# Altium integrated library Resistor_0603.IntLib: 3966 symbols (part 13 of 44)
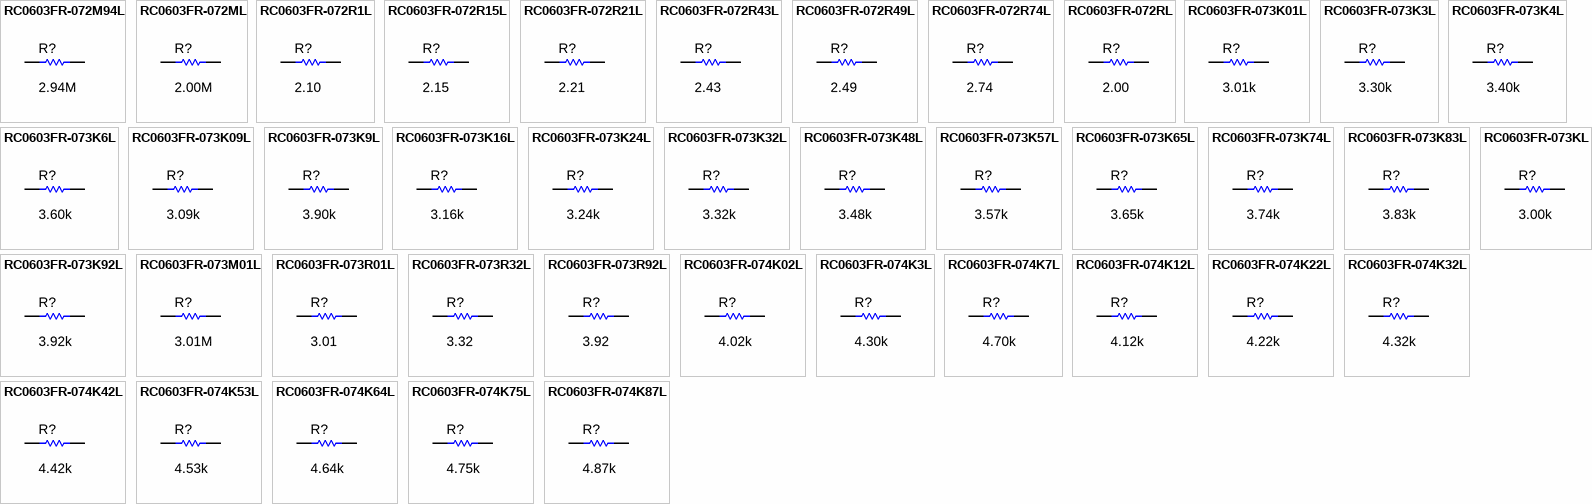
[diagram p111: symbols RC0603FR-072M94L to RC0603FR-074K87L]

## RC0603FR-074K53L
designator R?  ValueDisplayed: 4.53k  (hidden comment: RC0603FR-074K53L)
RES, 4.53 k, 1%, 0.1 W, 0603; Manufacturer: Yageo America; CompType: Resistor; Value: 4.53k; Res_ohm: 4530; Value_Code: 4k53; Tolerance_%: 1; Power_W: 0.1; Value2: 0.1W; VDC_V: 150; TempCo: 200 ppm/C; SizeArea_mm2: 1.28; SizeX_mm: 1.6; SizeY_mm: 0.8; EIA_Code: E96; U/M: EA; AEC Category: Q200
signal-integrity model Resistor
simulation model Resistor
footprint 0603
footprint 0603M
footprint 0603L
footprint 0603_HV
footprint 0603S
pins: 1, 2

## RC0603FR-074K64L
designator R?  ValueDisplayed: 4.64k  (hidden comment: RC0603FR-074K64L)
RES, 4.64 k, 1%, 0.1 W, 0603; Manufacturer: Yageo America; CompType: Resistor; Value: 4.64k; Res_ohm: 4640; Value_Code: 4k64; Tolerance_%: 1; Power_W: 0.1; Value2: 0.1W; VDC_V: 150; TempCo: 200 ppm/C; SizeArea_mm2: 1.28; SizeX_mm: 1.6; SizeY_mm: 0.8; EIA_Code: E96; U/M: EA; AEC Category: Q200; Green_Lifecycle: Active; Green_REACh: Passed
signal-integrity model Resistor
simulation model Resistor
footprint 0603
footprint 0603M
footprint 0603L
footprint 0603_HV
footprint 0603S
pins: 1, 2

## RC0603FR-074K75L
designator R?  ValueDisplayed: 4.75k  (hidden comment: RC0603FR-074K75L)
RES, 4.75 k, 1%, 0.1 W, 0603; Manufacturer: Yageo America; CompType: Resistor; Value: 4.75k; Res_ohm: 4750; Value_Code: 4k75; Tolerance_%: 1; Power_W: 0.1; Value2: 0.1W; VDC_V: 150; TempCo: 200 ppm/C; SizeArea_mm2: 1.28; SizeX_mm: 1.6; SizeY_mm: 0.8; EIA_Code: E96; U/M: EA; AEC Category: Q200
signal-integrity model Resistor
simulation model Resistor
footprint 0603
footprint 0603M
footprint 0603L
footprint 0603_HV
footprint 0603S
pins: 1, 2

## RC0603FR-074K87L
designator R?  ValueDisplayed: 4.87k  (hidden comment: RC0603FR-074K87L)
RES, 4.87 k, 1%, 0.1 W, 0603; Manufacturer: Yageo America; CompType: Resistor; Value: 4.87k; Res_ohm: 4870; Value_Code: 4k87; Tolerance_%: 1; Power_W: 0.1; Value2: 0.1W; VDC_V: 150; TempCo: 200 ppm/C; SizeArea_mm2: 1.28; SizeX_mm: 1.6; SizeY_mm: 0.8; EIA_Code: E96; U/M: EA; AEC Category: Q200; Green_Lifecycle: Active; Green_REACh: Passed
signal-integrity model Resistor
simulation model Resistor
footprint 0603
footprint 0603M
footprint 0603L
footprint 0603_HV
footprint 0603S
pins: 1, 2

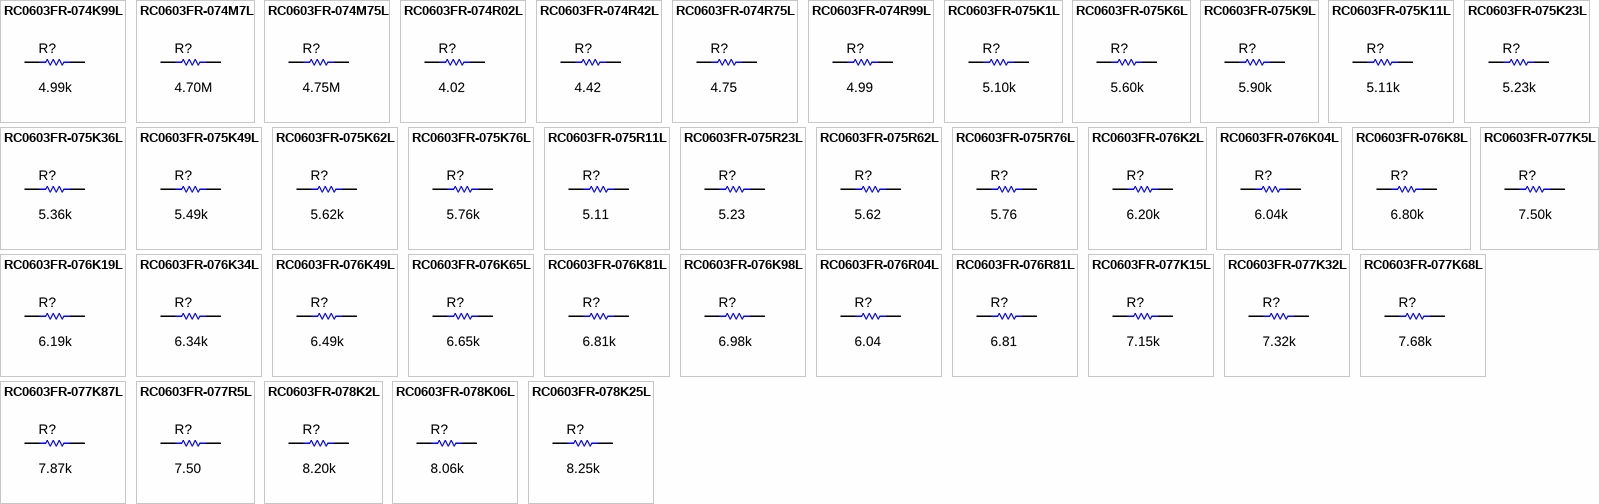
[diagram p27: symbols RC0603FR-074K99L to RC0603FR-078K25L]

## RC0603FR-074K99L
designator R?  ValueDisplayed: 4.99k  (hidden comment: RC0603FR-074K99L)
RES, 4.99 k, 1%, 0.1 W, 0603; Manufacturer: Yageo America; CompType: Resistor; Value: 4.99k; Res_ohm: 4990; Value_Code: 4k99; Tolerance_%: 1; Power_W: 0.1; Value2: 0.1W; VDC_V: 150; TempCo: 200 ppm/C; SizeArea_mm2: 1.28; SizeX_mm: 1.6; SizeY_mm: 0.8; EIA_Code: E96; U/M: EA; AEC Category: Q200; Green_Lifecycle: Active; Green_REACh: Passed
signal-integrity model Resistor
simulation model Resistor
footprint 0603
footprint 0603M
footprint 0603L
footprint 0603_HV
footprint 0603S
pins: 1, 2

## RC0603FR-074M7L
designator R?  ValueDisplayed: 4.70M  (hidden comment: RC0603FR-074M7L)
RES, 4.70 M, 1%, 0.1 W, 0603; Manufacturer: Yageo America; CompType: Resistor; Value: 4.70Meg; Res_ohm: 4700000; Value_Code: 4M70; Tolerance_%: 1; Power_W: 0.1; Value2: 0.1W; VDC_V: 150; TempCo: 200 ppm/C; SizeArea_mm2: 1.28; SizeX_mm: 1.6; SizeY_mm: 0.8; U/M: EA; AEC Category: Q200
signal-integrity model Resistor
simulation model Resistor
footprint 0603
footprint 0603M
footprint 0603L
footprint 0603_HV
footprint 0603S
pins: 1, 2

## RC0603FR-074M75L
designator R?  ValueDisplayed: 4.75M  (hidden comment: RC0603FR-074M75L)
RES, 4.75 M, 1%, 0.1 W, 0603; Manufacturer: Yageo America; CompType: Resistor; Value: 4.75Meg; Res_ohm: 4750000; Value_Code: 4M75; Tolerance_%: 1; Power_W: 0.1; Value2: 0.1W; VDC_V: 150; TempCo: 200 ppm/C; SizeArea_mm2: 1.28; SizeX_mm: 1.6; SizeY_mm: 0.8; EIA_Code: E96; U/M: EA; AEC Category: Q200
signal-integrity model Resistor
simulation model Resistor
footprint 0603
footprint 0603M
footprint 0603L
footprint 0603_HV
footprint 0603S
pins: 1, 2

## RC0603FR-074R02L
designator R?  ValueDisplayed: 4.02  (hidden comment: RC0603FR-074R02L)
RES, 4.02, 1%, 0.1 W, 0603; Manufacturer: Yageo America; CompType: Resistor; Value: 4.02; Value_Code: 4R02; Tolerance_%: 1; Power_W: 0.1; Value2: 0.1W; VDC_V: 150; TempCo: 200 ppm/C; SizeArea_mm2: 1.28; SizeX_mm: 1.6; SizeY_mm: 0.8; EIA_Code: E96; U/M: EA; AEC Category: Q200
signal-integrity model Resistor
simulation model Resistor
footprint 0603
footprint 0603M
footprint 0603L
footprint 0603_HV
footprint 0603S
pins: 1, 2

## RC0603FR-074R42L
designator R?  ValueDisplayed: 4.42  (hidden comment: RC0603FR-074R42L)
RES, 4.42, 1%, 0.1 W, 0603; Manufacturer: Yageo America; CompType: Resistor; Value: 4.42; Value_Code: 4R42; Tolerance_%: 1; Power_W: 0.1; Value2: 0.1W; VDC_V: 150; TempCo: 200 ppm/C; SizeArea_mm2: 1.28; SizeX_mm: 1.6; SizeY_mm: 0.8; EIA_Code: E96; U/M: EA; AEC Category: Q200
signal-integrity model Resistor
simulation model Resistor
footprint 0603
footprint 0603M
footprint 0603L
footprint 0603_HV
footprint 0603S
pins: 1, 2

## RC0603FR-074R75L
designator R?  ValueDisplayed: 4.75  (hidden comment: RC0603FR-074R75L)
RES, 4.75, 1%, 0.1 W, 0603; Manufacturer: Yageo America; CompType: Resistor; Value: 4.75; Value_Code: 4R75; Tolerance_%: 1; Power_W: 0.1; Value2: 0.1W; VDC_V: 150; TempCo: 200 ppm/C; SizeArea_mm2: 1.28; SizeX_mm: 1.6; SizeY_mm: 0.8; EIA_Code: E96; U/M: EA; AEC Category: Q200
signal-integrity model Resistor
simulation model Resistor
footprint 0603
footprint 0603M
footprint 0603L
footprint 0603_HV
footprint 0603S
pins: 1, 2

## RC0603FR-074R99L
designator R?  ValueDisplayed: 4.99  (hidden comment: RC0603FR-074R99L)
RES, 4.99, 1%, 0.1 W, 0603; Manufacturer: Yageo America; CompType: Resistor; Value: 4.99; Value_Code: 4R99; Tolerance_%: 1; Power_W: 0.1; Value2: 0.1W; VDC_V: 150; TempCo: 200 ppm/C; SizeArea_mm2: 1.28; SizeX_mm: 1.6; SizeY_mm: 0.8; EIA_Code: E96; U/M: EA; AEC Category: Q200; Green_Lifecycle: Active; Green_REACh: Passed
signal-integrity model Resistor
simulation model Resistor
footprint 0603
footprint 0603M
footprint 0603L
footprint 0603_HV
footprint 0603S
pins: 1, 2

## RC0603FR-075K1L
designator R?  ValueDisplayed: 5.10k  (hidden comment: RC0603FR-075K1L)
RES, 5.10 k, 1%, 0.1 W, 0603; Manufacturer: Yageo America; CompType: Resistor; Value: 5.10k; Res_ohm: 5100; Value_Code: 5k10; Tolerance_%: 1; Power_W: 0.1; Value2: 0.1W; VDC_V: 150; TempCo: 200 ppm/C; SizeArea_mm2: 1.28; SizeX_mm: 1.6; SizeY_mm: 0.8; U/M: EA; AEC Category: Q200; Green_Lifecycle: Active; Green_REACh: Passed
signal-integrity model Resistor
simulation model Resistor
footprint 0603
footprint 0603M
footprint 0603L
footprint 0603_HV
footprint 0603S
pins: 1, 2

## RC0603FR-075K6L
designator R?  ValueDisplayed: 5.60k  (hidden comment: RC0603FR-075K6L)
RES, 5.60 k, 1%, 0.1 W, 0603; Manufacturer: Yageo America; CompType: Resistor; Value: 5.60k; Res_ohm: 5600; Value_Code: 5k60; Tolerance_%: 1; Power_W: 0.1; Value2: 0.1W; VDC_V: 150; TempCo: 200 ppm/C; SizeArea_mm2: 1.28; SizeX_mm: 1.6; SizeY_mm: 0.8; U/M: EA; AEC Category: Q200; Green_Lifecycle: Active; Green_REACh: Passed
signal-integrity model Resistor
simulation model Resistor
footprint 0603
footprint 0603M
footprint 0603L
footprint 0603_HV
footprint 0603S
pins: 1, 2

## RC0603FR-075K9L
designator R?  ValueDisplayed: 5.90k  (hidden comment: RC0603FR-075K9L)
RES, 5.90 k, 1%, 0.1 W, 0603; Manufacturer: Yageo America; CompType: Resistor; Value: 5.90k; Res_ohm: 5900; Value_Code: 5k90; Tolerance_%: 1; Power_W: 0.1; Value2: 0.1W; VDC_V: 150; TempCo: 200 ppm/C; SizeArea_mm2: 1.28; SizeX_mm: 1.6; SizeY_mm: 0.8; EIA_Code: E96; U/M: EA; AEC Category: Q200; Green_Lifecycle: Active; Green_REACh: Passed
signal-integrity model Resistor
simulation model Resistor
footprint 0603
footprint 0603M
footprint 0603L
footprint 0603_HV
footprint 0603S
pins: 1, 2

## RC0603FR-075K11L
designator R?  ValueDisplayed: 5.11k  (hidden comment: RC0603FR-075K11L)
RES, 5.11 k, 1%, 0.1 W, 0603; Manufacturer: Yageo America; CompType: Resistor; Value: 5.11k; Res_ohm: 5110; Value_Code: 5k11; Tolerance_%: 1; Power_W: 0.1; Value2: 0.1W; VDC_V: 150; TempCo: 200 ppm/C; SizeArea_mm2: 1.28; SizeX_mm: 1.6; SizeY_mm: 0.8; EIA_Code: E96; U/M: EA; AEC Category: Q200; Green_Lifecycle: Active; Green_REACh: Passed
signal-integrity model Resistor
simulation model Resistor
footprint 0603
footprint 0603M
footprint 0603L
footprint 0603_HV
footprint 0603S
pins: 1, 2

## RC0603FR-075K23L
designator R?  ValueDisplayed: 5.23k  (hidden comment: RC0603FR-075K23L)
RES, 5.23 k, 1%, 0.1 W, 0603; Manufacturer: Yageo America; CompType: Resistor; Value: 5.23k; Res_ohm: 5230; Value_Code: 5k23; Tolerance_%: 1; Power_W: 0.1; Value2: 0.1W; VDC_V: 150; TempCo: 200 ppm/C; SizeArea_mm2: 1.28; SizeX_mm: 1.6; SizeY_mm: 0.8; EIA_Code: E96; U/M: EA; AEC Category: Q200; Green_Lifecycle: Active; Green_REACh: Passed
signal-integrity model Resistor
simulation model Resistor
footprint 0603
footprint 0603M
footprint 0603L
footprint 0603_HV
footprint 0603S
pins: 1, 2

## RC0603FR-075K36L
designator R?  ValueDisplayed: 5.36k  (hidden comment: RC0603FR-075K36L)
RES, 5.36 k, 1%, 0.1 W, 0603; Manufacturer: Yageo America; CompType: Resistor; Value: 5.36k; Res_ohm: 5360; Value_Code: 5k36; Tolerance_%: 1; Power_W: 0.1; Value2: 0.1W; VDC_V: 150; TempCo: 200 ppm/C; SizeArea_mm2: 1.28; SizeX_mm: 1.6; SizeY_mm: 0.8; EIA_Code: E96; U/M: EA; AEC Category: Q200; Green_Lifecycle: Active; Green_REACh: Passed
signal-integrity model Resistor
simulation model Resistor
footprint 0603
footprint 0603M
footprint 0603L
footprint 0603_HV
footprint 0603S
pins: 1, 2

## RC0603FR-075K49L
designator R?  ValueDisplayed: 5.49k  (hidden comment: RC0603FR-075K49L)
RES, 5.49 k, 1%, 0.1 W, 0603; Manufacturer: Yageo America; CompType: Resistor; Value: 5.49k; Res_ohm: 5490; Value_Code: 5k49; Tolerance_%: 1; Power_W: 0.1; Value2: 0.1W; VDC_V: 150; TempCo: 200 ppm/C; SizeArea_mm2: 1.28; SizeX_mm: 1.6; SizeY_mm: 0.8; EIA_Code: E96; U/M: EA; AEC Category: Q200
signal-integrity model Resistor
simulation model Resistor
footprint 0603
footprint 0603M
footprint 0603L
footprint 0603_HV
footprint 0603S
pins: 1, 2

## RC0603FR-075K62L
designator R?  ValueDisplayed: 5.62k  (hidden comment: RC0603FR-075K62L)
RES, 5.62 k, 1%, 0.1 W, 0603; Manufacturer: Yageo America; CompType: Resistor; Value: 5.62k; Res_ohm: 5620; Value_Code: 5k62; Tolerance_%: 1; Power_W: 0.1; Value2: 0.1W; VDC_V: 150; TempCo: 200 ppm/C; SizeArea_mm2: 1.28; SizeX_mm: 1.6; SizeY_mm: 0.8; EIA_Code: E96; U/M: EA; AEC Category: Q200; Green_Lifecycle: Active; Green_REACh: Passed
signal-integrity model Resistor
simulation model Resistor
footprint 0603
footprint 0603M
footprint 0603L
footprint 0603_HV
footprint 0603S
pins: 1, 2

## RC0603FR-075K76L
designator R?  ValueDisplayed: 5.76k  (hidden comment: RC0603FR-075K76L)
RES, 5.76 k, 1%, 0.1 W, 0603; Manufacturer: Yageo America; CompType: Resistor; Value: 5.76k; Res_ohm: 5760; Value_Code: 5k76; Tolerance_%: 1; Power_W: 0.1; Value2: 0.1W; VDC_V: 150; TempCo: 200 ppm/C; SizeArea_mm2: 1.28; SizeX_mm: 1.6; SizeY_mm: 0.8; EIA_Code: E96; U/M: EA; AEC Category: Q200
signal-integrity model Resistor
simulation model Resistor
footprint 0603
footprint 0603M
footprint 0603L
footprint 0603_HV
footprint 0603S
pins: 1, 2

## RC0603FR-075R11L
designator R?  ValueDisplayed: 5.11  (hidden comment: RC0603FR-075R11L)
RES, 5.11, 1%, 0.1 W, 0603; Manufacturer: Yageo America; CompType: Resistor; Value: 5.11; Value_Code: 5R11; Tolerance_%: 1; Power_W: 0.1; Value2: 0.1W; VDC_V: 150; TempCo: 200 ppm/C; SizeArea_mm2: 1.28; SizeX_mm: 1.6; SizeY_mm: 0.8; EIA_Code: E96; U/M: EA; AEC Category: Q200
signal-integrity model Resistor
simulation model Resistor
footprint 0603
footprint 0603M
footprint 0603L
footprint 0603_HV
footprint 0603S
pins: 1, 2

## RC0603FR-075R23L
designator R?  ValueDisplayed: 5.23  (hidden comment: RC0603FR-075R23L)
RES, 5.23, 1%, 0.1 W, 0603; Manufacturer: Yageo America; CompType: Resistor; Value: 5.23; Value_Code: 5R23; Tolerance_%: 1; Power_W: 0.1; Value2: 0.1W; VDC_V: 150; TempCo: 200 ppm/C; SizeArea_mm2: 1.28; SizeX_mm: 1.6; SizeY_mm: 0.8; EIA_Code: E96; U/M: EA; AEC Category: Q200
signal-integrity model Resistor
simulation model Resistor
footprint 0603
footprint 0603M
footprint 0603L
footprint 0603_HV
footprint 0603S
pins: 1, 2

## RC0603FR-075R62L
designator R?  ValueDisplayed: 5.62  (hidden comment: RC0603FR-075R62L)
RES, 5.62, 1%, 0.1 W, 0603; Manufacturer: Yageo America; CompType: Resistor; Value: 5.62; Value_Code: 5R62; Tolerance_%: 1; Power_W: 0.1; Value2: 0.1W; VDC_V: 150; TempCo: 200 ppm/C; SizeArea_mm2: 1.28; SizeX_mm: 1.6; SizeY_mm: 0.8; EIA_Code: E96; U/M: EA; AEC Category: Q200
signal-integrity model Resistor
simulation model Resistor
footprint 0603
footprint 0603M
footprint 0603L
footprint 0603_HV
footprint 0603S
pins: 1, 2

## RC0603FR-075R76L
designator R?  ValueDisplayed: 5.76  (hidden comment: RC0603FR-075R76L)
RES, 5.76, 1%, 0.1 W, 0603; Manufacturer: Yageo America; CompType: Resistor; Value: 5.76; Value_Code: 5R76; Tolerance_%: 1; Power_W: 0.1; Value2: 0.1W; VDC_V: 150; TempCo: 200 ppm/C; SizeArea_mm2: 1.28; SizeX_mm: 1.6; SizeY_mm: 0.8; EIA_Code: E96; U/M: EA; AEC Category: Q200
signal-integrity model Resistor
simulation model Resistor
footprint 0603
footprint 0603M
footprint 0603L
footprint 0603_HV
footprint 0603S
pins: 1, 2

## RC0603FR-076K2L
designator R?  ValueDisplayed: 6.20k  (hidden comment: RC0603FR-076K2L)
RES, 6.20 k, 1%, 0.1 W, 0603; Manufacturer: Yageo America; CompType: Resistor; Value: 6.20k; Res_ohm: 6200; Value_Code: 6k20; Tolerance_%: 1; Power_W: 0.1; Value2: 0.1W; VDC_V: 150; TempCo: 200 ppm/C; SizeArea_mm2: 1.28; SizeX_mm: 1.6; SizeY_mm: 0.8; U/M: EA; AEC Category: Q200
signal-integrity model Resistor
simulation model Resistor
footprint 0603
footprint 0603M
footprint 0603L
footprint 0603_HV
footprint 0603S
pins: 1, 2

## RC0603FR-076K04L
designator R?  ValueDisplayed: 6.04k  (hidden comment: RC0603FR-076K04L)
RES, 6.04 k, 1%, 0.1 W, 0603; Manufacturer: Yageo America; CompType: Resistor; Value: 6.04k; Res_ohm: 6040; Value_Code: 6k04; Tolerance_%: 1; Power_W: 0.1; Value2: 0.1W; VDC_V: 150; TempCo: 200 ppm/C; SizeArea_mm2: 1.28; SizeX_mm: 1.6; SizeY_mm: 0.8; EIA_Code: E96; U/M: EA; AEC Category: Q200; Green_Lifecycle: Active; Green_REACh: Passed
signal-integrity model Resistor
simulation model Resistor
footprint 0603
footprint 0603M
footprint 0603L
footprint 0603_HV
footprint 0603S
pins: 1, 2

## RC0603FR-076K8L
designator R?  ValueDisplayed: 6.80k  (hidden comment: RC0603FR-076K8L)
RES, 6.80 k, 1%, 0.1 W, 0603; Manufacturer: Yageo America; CompType: Resistor; Value: 6.80k; Res_ohm: 6800; Value_Code: 6k80; Tolerance_%: 1; Power_W: 0.1; Value2: 0.1W; VDC_V: 150; TempCo: 200 ppm/C; SizeArea_mm2: 1.28; SizeX_mm: 1.6; SizeY_mm: 0.8; U/M: EA; AEC Category: Q200; Green_Lifecycle: Active; Green_REACh: Passed
signal-integrity model Resistor
simulation model Resistor
footprint 0603
footprint 0603M
footprint 0603L
footprint 0603_HV
footprint 0603S
pins: 1, 2

## RC0603FR-076K19L
designator R?  ValueDisplayed: 6.19k  (hidden comment: RC0603FR-076K19L)
RES, 6.19 k, 1%, 0.1 W, 0603; Manufacturer: Yageo America; CompType: Resistor; Value: 6.19k; Res_ohm: 6190; Value_Code: 6k19; Tolerance_%: 1; Power_W: 0.1; Value2: 0.1W; VDC_V: 150; TempCo: 200 ppm/C; SizeArea_mm2: 1.28; SizeX_mm: 1.6; SizeY_mm: 0.8; EIA_Code: E96; U/M: EA; AEC Category: Q200
signal-integrity model Resistor
simulation model Resistor
footprint 0603
footprint 0603M
footprint 0603L
footprint 0603_HV
footprint 0603S
pins: 1, 2

## RC0603FR-076K34L
designator R?  ValueDisplayed: 6.34k  (hidden comment: RC0603FR-076K34L)
RES, 6.34 k, 1%, 0.1 W, 0603; Manufacturer: Yageo America; CompType: Resistor; Value: 6.34k; Res_ohm: 6340; Value_Code: 6k34; Tolerance_%: 1; Power_W: 0.1; Value2: 0.1W; VDC_V: 150; TempCo: 200 ppm/C; SizeArea_mm2: 1.28; SizeX_mm: 1.6; SizeY_mm: 0.8; EIA_Code: E96; U/M: EA; AEC Category: Q200
signal-integrity model Resistor
simulation model Resistor
footprint 0603
footprint 0603M
footprint 0603L
footprint 0603_HV
footprint 0603S
pins: 1, 2

## RC0603FR-076K49L
designator R?  ValueDisplayed: 6.49k  (hidden comment: RC0603FR-076K49L)
RES, 6.49 k, 1%, 0.1 W, 0603; Manufacturer: Yageo America; CompType: Resistor; Value: 6.49k; Res_ohm: 6490; Value_Code: 6k49; Tolerance_%: 1; Power_W: 0.1; Value2: 0.1W; VDC_V: 150; TempCo: 200 ppm/C; SizeArea_mm2: 1.28; SizeX_mm: 1.6; SizeY_mm: 0.8; EIA_Code: E96; U/M: EA; AEC Category: Q200; Green_Lifecycle: Not Set; Green_REACh: Incomplete
signal-integrity model Resistor
simulation model Resistor
footprint 0603
footprint 0603M
footprint 0603L
footprint 0603_HV
footprint 0603S
pins: 1, 2

## RC0603FR-076K65L
designator R?  ValueDisplayed: 6.65k  (hidden comment: RC0603FR-076K65L)
RES, 6.65 k, 1%, 0.1 W, 0603; Manufacturer: Yageo America; CompType: Resistor; Value: 6.65k; Res_ohm: 6650; Value_Code: 6k65; Tolerance_%: 1; Power_W: 0.1; Value2: 0.1W; VDC_V: 150; TempCo: 200 ppm/C; SizeArea_mm2: 1.28; SizeX_mm: 1.6; SizeY_mm: 0.8; EIA_Code: E96; U/M: EA; AEC Category: Q200; Green_Lifecycle: Active; Green_REACh: Passed
signal-integrity model Resistor
simulation model Resistor
footprint 0603
footprint 0603M
footprint 0603L
footprint 0603_HV
footprint 0603S
pins: 1, 2

## RC0603FR-076K81L
designator R?  ValueDisplayed: 6.81k  (hidden comment: RC0603FR-076K81L)
RES, 6.81 k, 1%, 0.1 W, 0603; Manufacturer: Yageo America; CompType: Resistor; Value: 6.81k; Res_ohm: 6810; Value_Code: 6k81; Tolerance_%: 1; Power_W: 0.1; Value2: 0.1W; VDC_V: 150; TempCo: 200 ppm/C; SizeArea_mm2: 1.28; SizeX_mm: 1.6; SizeY_mm: 0.8; EIA_Code: E96; U/M: EA; AEC Category: Q200
signal-integrity model Resistor
simulation model Resistor
footprint 0603
footprint 0603M
footprint 0603L
footprint 0603_HV
footprint 0603S
pins: 1, 2

## RC0603FR-076K98L
designator R?  ValueDisplayed: 6.98k  (hidden comment: RC0603FR-076K98L)
RES, 6.98 k, 1%, 0.1 W, 0603; Manufacturer: Yageo America; CompType: Resistor; Value: 6.98k; Res_ohm: 6980; Value_Code: 6k98; Tolerance_%: 1; Power_W: 0.1; Value2: 0.1W; VDC_V: 150; TempCo: 200 ppm/C; SizeArea_mm2: 1.28; SizeX_mm: 1.6; SizeY_mm: 0.8; EIA_Code: E96; U/M: EA; AEC Category: Q200; Green_Lifecycle: Active; Green_REACh: Passed
signal-integrity model Resistor
simulation model Resistor
footprint 0603
footprint 0603M
footprint 0603L
footprint 0603_HV
footprint 0603S
pins: 1, 2

## RC0603FR-076R04L
designator R?  ValueDisplayed: 6.04  (hidden comment: RC0603FR-076R04L)
RES, 6.04, 1%, 0.1 W, 0603; Manufacturer: Yageo America; CompType: Resistor; Value: 6.04; Value_Code: 6R04; Tolerance_%: 1; Power_W: 0.1; Value2: 0.1W; VDC_V: 150; TempCo: 200 ppm/C; SizeArea_mm2: 1.28; SizeX_mm: 1.6; SizeY_mm: 0.8; EIA_Code: E96; U/M: EA; AEC Category: Q200
signal-integrity model Resistor
simulation model Resistor
footprint 0603
footprint 0603M
footprint 0603L
footprint 0603_HV
footprint 0603S
pins: 1, 2

## RC0603FR-076R81L
designator R?  ValueDisplayed: 6.81  (hidden comment: RC0603FR-076R81L)
RES, 6.81, 1%, 0.1 W, 0603; Manufacturer: Yageo America; CompType: Resistor; Value: 6.81; Value_Code: 6R81; Tolerance_%: 1; Power_W: 0.1; Value2: 0.1W; VDC_V: 150; TempCo: 200 ppm/C; SizeArea_mm2: 1.28; SizeX_mm: 1.6; SizeY_mm: 0.8; EIA_Code: E96; U/M: EA; AEC Category: Q200
signal-integrity model Resistor
simulation model Resistor
footprint 0603
footprint 0603M
footprint 0603L
footprint 0603_HV
footprint 0603S
pins: 1, 2

## RC0603FR-077K5L
designator R?  ValueDisplayed: 7.50k  (hidden comment: RC0603FR-077K5L)
RES, 7.50 k, 1%, 0.1 W, 0603; Manufacturer: Yageo America; CompType: Resistor; Value: 7.50k; Res_ohm: 7500; Value_Code: 7k50; Tolerance_%: 1; Power_W: 0.1; Value2: 0.1W; VDC_V: 150; TempCo: 200 ppm/C; SizeArea_mm2: 1.28; SizeX_mm: 1.6; SizeY_mm: 0.8; EIA_Code: E96; U/M: EA; AEC Category: Q200; Green_Lifecycle: Active; Green_REACh: Passed
signal-integrity model Resistor
simulation model Resistor
footprint 0603
footprint 0603M
footprint 0603L
footprint 0603_HV
footprint 0603S
pins: 1, 2

## RC0603FR-077K15L
designator R?  ValueDisplayed: 7.15k  (hidden comment: RC0603FR-077K15L)
RES, 7.15 k, 1%, 0.1 W, 0603; Manufacturer: Yageo America; CompType: Resistor; Value: 7.15k; Res_ohm: 7150; Value_Code: 7k15; Tolerance_%: 1; Power_W: 0.1; Value2: 0.1W; VDC_V: 150; TempCo: 200 ppm/C; SizeArea_mm2: 1.28; SizeX_mm: 1.6; SizeY_mm: 0.8; EIA_Code: E96; U/M: EA; AEC Category: Q200; Green_Lifecycle: Active; Green_REACh: Passed
signal-integrity model Resistor
simulation model Resistor
footprint 0603
footprint 0603M
footprint 0603L
footprint 0603_HV
footprint 0603S
pins: 1, 2

## RC0603FR-077K32L
designator R?  ValueDisplayed: 7.32k  (hidden comment: RC0603FR-077K32L)
RES, 7.32 k, 1%, 0.1 W, 0603; Manufacturer: Yageo America; CompType: Resistor; Value: 7.32k; Res_ohm: 7320; Value_Code: 7k32; Tolerance_%: 1; Power_W: 0.1; Value2: 0.1W; VDC_V: 150; TempCo: 200 ppm/C; SizeArea_mm2: 1.28; SizeX_mm: 1.6; SizeY_mm: 0.8; EIA_Code: E96; U/M: EA; AEC Category: Q200
signal-integrity model Resistor
simulation model Resistor
footprint 0603
footprint 0603M
footprint 0603L
footprint 0603_HV
footprint 0603S
pins: 1, 2

## RC0603FR-077K68L
designator R?  ValueDisplayed: 7.68k  (hidden comment: RC0603FR-077K68L)
RES, 7.68 k, 1%, 0.1 W, 0603; Manufacturer: Yageo America; CompType: Resistor; Value: 7.68k; Res_ohm: 7680; Value_Code: 7k68; Tolerance_%: 1; Power_W: 0.1; Value2: 0.1W; VDC_V: 150; TempCo: 200 ppm/C; SizeArea_mm2: 1.28; SizeX_mm: 1.6; SizeY_mm: 0.8; EIA_Code: E96; U/M: EA; AEC Category: Q200; Green_Lifecycle: Active; Green_REACh: Passed
signal-integrity model Resistor
simulation model Resistor
footprint 0603
footprint 0603M
footprint 0603L
footprint 0603_HV
footprint 0603S
pins: 1, 2

## RC0603FR-077K87L
designator R?  ValueDisplayed: 7.87k  (hidden comment: RC0603FR-077K87L)
RES, 7.87 k, 1%, 0.1 W, 0603; Manufacturer: Yageo America; CompType: Resistor; Value: 7.87k; Res_ohm: 7870; Value_Code: 7k87; Tolerance_%: 1; Power_W: 0.1; Value2: 0.1W; VDC_V: 150; TempCo: 200 ppm/C; SizeArea_mm2: 1.28; SizeX_mm: 1.6; SizeY_mm: 0.8; EIA_Code: E96; U/M: EA; AEC Category: Q200
signal-integrity model Resistor
simulation model Resistor
footprint 0603
footprint 0603M
footprint 0603L
footprint 0603_HV
footprint 0603S
pins: 1, 2

## RC0603FR-077R5L
designator R?  ValueDisplayed: 7.50  (hidden comment: RC0603FR-077R5L)
RES, 7.50, 1%, 0.1 W, 0603; Manufacturer: Yageo America; CompType: Resistor; Value: 7.50; Res_ohm: 7.5; Value_Code: 7R50; Tolerance_%: 1; Power_W: 0.1; Value2: 0.1W; VDC_V: 150; TempCo: 200 ppm/C; SizeArea_mm2: 1.28; SizeX_mm: 1.6; SizeY_mm: 0.8; EIA_Code: E96; U/M: EA; AEC Category: Q200
signal-integrity model Resistor
simulation model Resistor
footprint 0603
footprint 0603M
footprint 0603L
footprint 0603_HV
footprint 0603S
pins: 1, 2

## RC0603FR-078K2L
designator R?  ValueDisplayed: 8.20k  (hidden comment: RC0603FR-078K2L)
RES, 8.20 k, 1%, 0.1 W, 0603; Manufacturer: Yageo America; CompType: Resistor; Value: 8.20k; Res_ohm: 8200; Value_Code: 8k20; Tolerance_%: 1; Power_W: 0.1; Value2: 0.1W; VDC_V: 150; TempCo: 200 ppm/C; SizeArea_mm2: 1.28; SizeX_mm: 1.6; SizeY_mm: 0.8; U/M: EA; AEC Category: Q200; Green_Lifecycle: Active; Green_REACh: Passed
signal-integrity model Resistor
simulation model Resistor
footprint 0603
footprint 0603M
footprint 0603L
footprint 0603_HV
footprint 0603S
pins: 1, 2

## RC0603FR-078K06L
designator R?  ValueDisplayed: 8.06k  (hidden comment: RC0603FR-078K06L)
RES, 8.06 k, 1%, 0.1 W, 0603; Manufacturer: Yageo America; CompType: Resistor; Value: 8.06k; Res_ohm: 8060; Value_Code: 8k06; Tolerance_%: 1; Power_W: 0.1; Value2: 0.1W; VDC_V: 150; TempCo: 200 ppm/C; SizeArea_mm2: 1.28; SizeX_mm: 1.6; SizeY_mm: 0.8; EIA_Code: E96; U/M: EA; AEC Category: Q200; Green_Lifecycle: Active; Green_REACh: Passed
signal-integrity model Resistor
simulation model Resistor
footprint 0603
footprint 0603M
footprint 0603L
footprint 0603_HV
footprint 0603S
pins: 1, 2

## RC0603FR-078K25L
designator R?  ValueDisplayed: 8.25k  (hidden comment: RC0603FR-078K25L)
RES, 8.25 k, 1%, 0.1 W, 0603; Manufacturer: Yageo America; CompType: Resistor; Value: 8.25k; Res_ohm: 8250; Value_Code: 8k25; Tolerance_%: 1; Power_W: 0.1; Value2: 0.1W; VDC_V: 150; TempCo: 200 ppm/C; SizeArea_mm2: 1.28; SizeX_mm: 1.6; SizeY_mm: 0.8; EIA_Code: E96; U/M: EA; AEC Category: Q200
signal-integrity model Resistor
simulation model Resistor
footprint 0603
footprint 0603M
footprint 0603L
footprint 0603_HV
footprint 0603S
pins: 1, 2

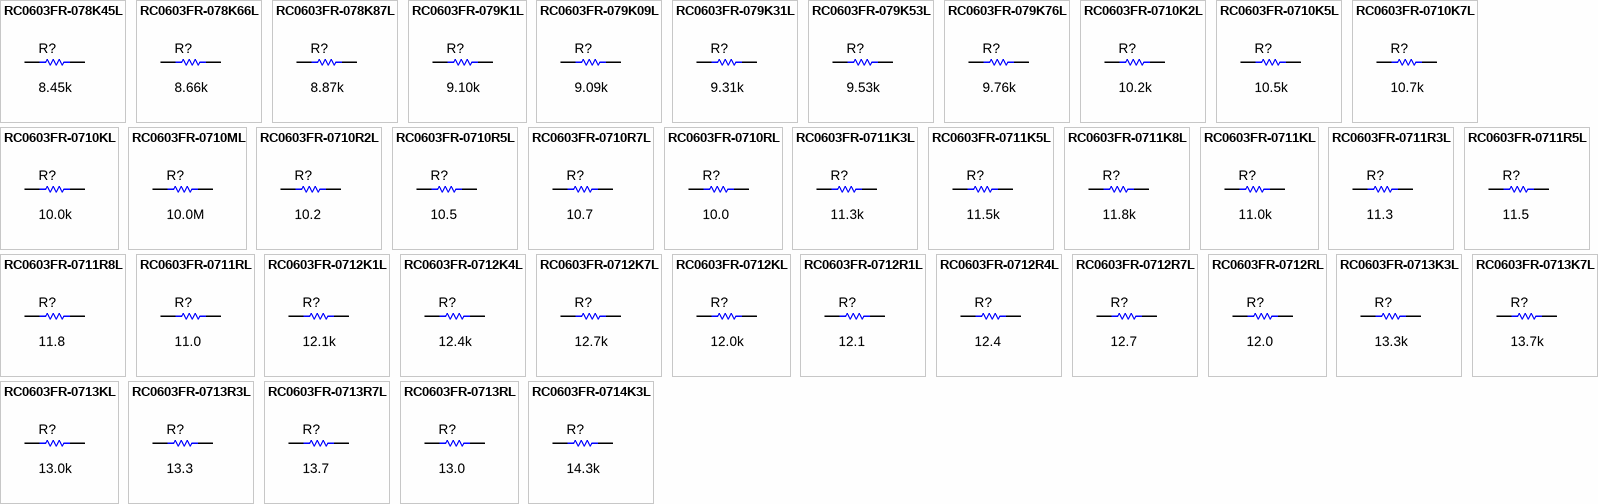
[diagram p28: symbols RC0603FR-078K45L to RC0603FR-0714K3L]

## RC0603FR-078K45L
designator R?  ValueDisplayed: 8.45k  (hidden comment: RC0603FR-078K45L)
RES, 8.45 k, 1%, 0.1 W, 0603; Manufacturer: Yageo America; CompType: Resistor; Value: 8.45k; Res_ohm: 8450; Value_Code: 8k45; Tolerance_%: 1; Power_W: 0.1; Value2: 0.1W; VDC_V: 150; TempCo: 200 ppm/C; SizeArea_mm2: 1.28; SizeX_mm: 1.6; SizeY_mm: 0.8; EIA_Code: E96; U/M: EA; AEC Category: Q200; AEC Qualified: N; Green_Lifecycle: Active; Green_REACh: Passed
signal-integrity model Resistor
simulation model Resistor
footprint 0603
footprint 0603M
footprint 0603L
footprint 0603_HV
footprint 0603S
pins: 1, 2

## RC0603FR-078K66L
designator R?  ValueDisplayed: 8.66k  (hidden comment: RC0603FR-078K66L)
RES, 8.66 k, 1%, 0.1 W, 0603; Manufacturer: Yageo America; CompType: Resistor; Value: 8.66k; Res_ohm: 8660; Value_Code: 8k66; Tolerance_%: 1; Power_W: 0.1; Value2: 0.1W; VDC_V: 150; TempCo: 200 ppm/C; SizeArea_mm2: 1.28; SizeX_mm: 1.6; SizeY_mm: 0.8; EIA_Code: E96; U/M: EA; AEC Category: Q200
signal-integrity model Resistor
simulation model Resistor
footprint 0603
footprint 0603M
footprint 0603L
footprint 0603_HV
footprint 0603S
pins: 1, 2

## RC0603FR-078K87L
designator R?  ValueDisplayed: 8.87k  (hidden comment: RC0603FR-078K87L)
RES, 8.87 k, 1%, 0.1 W, 0603; Manufacturer: Yageo America; CompType: Resistor; Value: 8.87k; Res_ohm: 8870; Value_Code: 8k87; Tolerance_%: 1; Power_W: 0.1; Value2: 0.1W; VDC_V: 150; TempCo: 200 ppm/C; SizeArea_mm2: 1.28; SizeX_mm: 1.6; SizeY_mm: 0.8; EIA_Code: E96; U/M: EA; AEC Category: Q200
signal-integrity model Resistor
simulation model Resistor
footprint 0603
footprint 0603M
footprint 0603L
footprint 0603_HV
footprint 0603S
pins: 1, 2

## RC0603FR-079K1L
designator R?  ValueDisplayed: 9.10k  (hidden comment: RC0603FR-079K1L)
RES, 9.10 k, 1%, 0.1 W, 0603; Manufacturer: Yageo America; CompType: Resistor; Value: 9.10k; Res_ohm: 9100; Value_Code: 9k10; Tolerance_%: 1; Power_W: 0.1; Value2: 0.1W; VDC_V: 150; TempCo: 200 ppm/C; SizeArea_mm2: 1.28; SizeX_mm: 1.6; SizeY_mm: 0.8; U/M: EA; AEC Category: Q200; Green_Lifecycle: Active; Green_REACh: Passed
signal-integrity model Resistor
simulation model Resistor
footprint 0603
footprint 0603M
footprint 0603L
footprint 0603_HV
footprint 0603S
pins: 1, 2

## RC0603FR-079K09L
designator R?  ValueDisplayed: 9.09k  (hidden comment: RC0603FR-079K09L)
RES, 9.09 k, 1%, 0.1 W, 0603; Manufacturer: Yageo America; CompType: Resistor; Value: 9.09k; Res_ohm: 9090; Value_Code: 9k09; Tolerance_%: 1; Power_W: 0.1; Value2: 0.1W; VDC_V: 150; TempCo: 200 ppm/C; SizeArea_mm2: 1.28; SizeX_mm: 1.6; SizeY_mm: 0.8; EIA_Code: E96; U/M: EA; AEC Category: Q200; Green_Lifecycle: Active; Green_REACh: Passed
signal-integrity model Resistor
simulation model Resistor
footprint 0603
footprint 0603M
footprint 0603L
footprint 0603_HV
footprint 0603S
pins: 1, 2

## RC0603FR-079K31L
designator R?  ValueDisplayed: 9.31k  (hidden comment: RC0603FR-079K31L)
RES, 9.31 k, 1%, 0.1 W, 0603; Manufacturer: Yageo America; CompType: Resistor; Value: 9.31k; Res_ohm: 9310; Value_Code: 9k31; Tolerance_%: 1; Power_W: 0.1; Value2: 0.1W; VDC_V: 150; TempCo: 200 ppm/C; SizeArea_mm2: 1.28; SizeX_mm: 1.6; SizeY_mm: 0.8; EIA_Code: E96; U/M: EA; AEC Category: Q200
signal-integrity model Resistor
simulation model Resistor
footprint 0603
footprint 0603M
footprint 0603L
footprint 0603_HV
footprint 0603S
pins: 1, 2

## RC0603FR-079K53L
designator R?  ValueDisplayed: 9.53k  (hidden comment: RC0603FR-079K53L)
RES, 9.53 k, 1%, 0.1 W, 0603; Manufacturer: Yageo America; CompType: Resistor; Value: 9.53k; Res_ohm: 9530; Value_Code: 9k53; Tolerance_%: 1; Power_W: 0.1; Value2: 0.1W; VDC_V: 150; TempCo: 200 ppm/C; SizeArea_mm2: 1.28; SizeX_mm: 1.6; SizeY_mm: 0.8; EIA_Code: E96; U/M: EA; AEC Category: Q200
signal-integrity model Resistor
simulation model Resistor
footprint 0603
footprint 0603M
footprint 0603L
footprint 0603_HV
footprint 0603S
pins: 1, 2

## RC0603FR-079K76L
designator R?  ValueDisplayed: 9.76k  (hidden comment: RC0603FR-079K76L)
RES, 9.76 k, 1%, 0.1 W, 0603; Manufacturer: Yageo America; CompType: Resistor; Value: 9.76k; Res_ohm: 9760; Value_Code: 9k76; Tolerance_%: 1; Power_W: 0.1; Value2: 0.1W; VDC_V: 150; TempCo: 200 ppm/C; SizeArea_mm2: 1.28; SizeX_mm: 1.6; SizeY_mm: 0.8; EIA_Code: E96; U/M: EA; AEC Category: Q200
signal-integrity model Resistor
simulation model Resistor
footprint 0603
footprint 0603M
footprint 0603L
footprint 0603_HV
footprint 0603S
pins: 1, 2

## RC0603FR-0710K2L
designator R?  ValueDisplayed: 10.2k  (hidden comment: RC0603FR-0710K2L)
RES, 10.2 k, 1%, 0.1 W, 0603; Manufacturer: Yageo America; CompType: Resistor; Value: 10.2k; Res_ohm: 10200; Value_Code: 10k2; Tolerance_%: 1; Power_W: 0.1; Value2: 0.1W; VDC_V: 150; TempCo: 200 ppm/C; SizeArea_mm2: 1.28; SizeX_mm: 1.6; SizeY_mm: 0.8; EIA_Code: E96; U/M: EA; AEC Category: Q200; Green_Lifecycle: Active; Green_REACh: Passed
signal-integrity model Resistor
simulation model Resistor
footprint 0603
footprint 0603M
footprint 0603L
footprint 0603_HV
footprint 0603S
pins: 1, 2

## RC0603FR-0710K5L
designator R?  ValueDisplayed: 10.5k  (hidden comment: RC0603FR-0710K5L)
RES, 10.5 k, 1%, 0.1 W, 0603; Manufacturer: Yageo America; CompType: Resistor; Value: 10.5k; Res_ohm: 10500; Value_Code: 10k5; Tolerance_%: 1; Power_W: 0.1; Value2: 0.1W; VDC_V: 150; TempCo: 200 ppm/C; SizeArea_mm2: 1.28; SizeX_mm: 1.6; SizeY_mm: 0.8; EIA_Code: E96; U/M: EA; AEC Category: Q200; Green_Lifecycle: Active; Green_REACh: Passed
signal-integrity model Resistor
simulation model Resistor
footprint 0603
footprint 0603M
footprint 0603L
footprint 0603_HV
footprint 0603S
pins: 1, 2

## RC0603FR-0710K7L
designator R?  ValueDisplayed: 10.7k  (hidden comment: RC0603FR-0710K7L)
RES, 10.7 k, 1%, 0.1 W, 0603; Manufacturer: Yageo America; CompType: Resistor; Value: 10.7k; Res_ohm: 10700; Value_Code: 10k7; Tolerance_%: 1; Power_W: 0.1; Value2: 0.1W; VDC_V: 150; TempCo: 200 ppm/C; SizeArea_mm2: 1.28; SizeX_mm: 1.6; SizeY_mm: 0.8; EIA_Code: E96; U/M: EA; AEC Category: Q200
signal-integrity model Resistor
simulation model Resistor
footprint 0603
footprint 0603M
footprint 0603L
footprint 0603_HV
footprint 0603S
pins: 1, 2

## RC0603FR-0710KL
designator R?  ValueDisplayed: 10.0k  (hidden comment: RC0603FR-0710KL)
RES, 10.0 k, 1%, 0.1 W, 0603; Manufacturer: Yageo America; CompType: Resistor; Value: 10.0k; Res_ohm: 10000; Value_Code: 10k0; Tolerance_%: 1; Power_W: 0.1; Value2: 0.1W; VDC_V: 150; TempCo: 200 ppm/C; SizeArea_mm2: 1.28; SizeX_mm: 1.6; SizeY_mm: 0.8; EIA_Code: E96; U/M: EA; AEC Category: Q200; Green_Lifecycle: Active; Green_REACh: Passed
signal-integrity model Resistor
simulation model Resistor
footprint 0603
footprint 0603M
footprint 0603L
footprint 0603_HV
footprint 0603S
pins: 1, 2

## RC0603FR-0710ML
designator R?  ValueDisplayed: 10.0M  (hidden comment: RC0603FR-0710ML)
RES, 10.0 M, 1%, 0.1 W, 0603; Manufacturer: Yageo America; CompType: Resistor; Value: 10.0Meg; Res_ohm: 10000000; Value_Code: 10M0; Tolerance_%: 1; Power_W: 0.1; Value2: 0.1W; VDC_V: 150; TempCo: 200 ppm/C; SizeArea_mm2: 1.28; SizeX_mm: 1.6; SizeY_mm: 0.8; EIA_Code: E96; U/M: EA; AEC Category: Q200; Green_Lifecycle: Active; Green_REACh: Passed
signal-integrity model Resistor
simulation model Resistor
footprint 0603
footprint 0603M
footprint 0603L
footprint 0603_HV
footprint 0603S
pins: 1, 2

## RC0603FR-0710R2L
designator R?  ValueDisplayed: 10.2  (hidden comment: RC0603FR-0710R2L)
RES, 10.2, 1%, 0.1 W, 0603; Manufacturer: Yageo America; CompType: Resistor; Value: 10.2; Value_Code: 10R2; Tolerance_%: 1; Power_W: 0.1; Value2: 0.1W; VDC_V: 150; TempCo: 200 ppm/C; SizeArea_mm2: 1.28; SizeX_mm: 1.6; SizeY_mm: 0.8; EIA_Code: E96; U/M: EA; AEC Category: Q200
signal-integrity model Resistor
simulation model Resistor
footprint 0603
footprint 0603M
footprint 0603L
footprint 0603_HV
footprint 0603S
pins: 1, 2

## RC0603FR-0710R5L
designator R?  ValueDisplayed: 10.5  (hidden comment: RC0603FR-0710R5L)
RES, 10.5, 1%, 0.1 W, 0603; Manufacturer: Yageo America; CompType: Resistor; Value: 10.5; Value_Code: 10R5; Tolerance_%: 1; Power_W: 0.1; Value2: 0.1W; VDC_V: 150; TempCo: 200 ppm/C; SizeArea_mm2: 1.28; SizeX_mm: 1.6; SizeY_mm: 0.8; EIA_Code: E96; U/M: EA; AEC Category: Q200
signal-integrity model Resistor
simulation model Resistor
footprint 0603
footprint 0603M
footprint 0603L
footprint 0603_HV
footprint 0603S
pins: 1, 2

## RC0603FR-0710R7L
designator R?  ValueDisplayed: 10.7  (hidden comment: RC0603FR-0710R7L)
RES, 10.7, 1%, 0.1 W, 0603; Manufacturer: Yageo America; CompType: Resistor; Value: 10.7; Value_Code: 10R7; Tolerance_%: 1; Power_W: 0.1; Value2: 0.1W; VDC_V: 150; TempCo: 200 ppm/C; SizeArea_mm2: 1.28; SizeX_mm: 1.6; SizeY_mm: 0.8; EIA_Code: E96; U/M: EA; AEC Category: Q200
signal-integrity model Resistor
simulation model Resistor
footprint 0603
footprint 0603M
footprint 0603L
footprint 0603_HV
footprint 0603S
pins: 1, 2

## RC0603FR-0710RL
designator R?  ValueDisplayed: 10.0  (hidden comment: RC0603FR-0710RL)
RES, 10.0, 1%, 0.1 W, 0603; Manufacturer: Yageo America; CompType: Resistor; Value: 10.0; Res_ohm: 10; Value_Code: 10R0; Tolerance_%: 1; Power_W: 0.1; Value2: 0.1W; VDC_V: 150; TempCo: 200 ppm/C; SizeArea_mm2: 1.28; SizeX_mm: 1.6; SizeY_mm: 0.8; EIA_Code: E96; U/M: EA; AEC Category: Q200; Green_Lifecycle: Active; Green_REACh: Passed
signal-integrity model Resistor
simulation model Resistor
footprint 0603
footprint 0603M
footprint 0603L
footprint 0603_HV
footprint 0603S
pins: 1, 2

## RC0603FR-0711K3L
designator R?  ValueDisplayed: 11.3k  (hidden comment: RC0603FR-0711K3L)
RES, 11.3 k, 1%, 0.1 W, 0603; Manufacturer: Yageo America; CompType: Resistor; Value: 11.3k; Res_ohm: 11300; Value_Code: 11k3; Tolerance_%: 1; Power_W: 0.1; Value2: 0.1W; VDC_V: 150; TempCo: 200 ppm/C; SizeArea_mm2: 1.28; SizeX_mm: 1.6; SizeY_mm: 0.8; EIA_Code: E96; U/M: EA; AEC Category: Q200
signal-integrity model Resistor
simulation model Resistor
footprint 0603
footprint 0603M
footprint 0603L
footprint 0603_HV
footprint 0603S
pins: 1, 2

## RC0603FR-0711K5L
designator R?  ValueDisplayed: 11.5k  (hidden comment: RC0603FR-0711K5L)
RES, 11.5 k, 1%, 0.1 W, 0603; Manufacturer: Yageo America; CompType: Resistor; Value: 11.5k; Res_ohm: 11500; Value_Code: 11k5; Tolerance_%: 1; Power_W: 0.1; Value2: 0.1W; VDC_V: 150; TempCo: 200 ppm/C; SizeArea_mm2: 1.28; SizeX_mm: 1.6; SizeY_mm: 0.8; EIA_Code: E96; U/M: EA; AEC Category: Q200
signal-integrity model Resistor
simulation model Resistor
footprint 0603
footprint 0603M
footprint 0603L
footprint 0603_HV
footprint 0603S
pins: 1, 2

## RC0603FR-0711K8L
designator R?  ValueDisplayed: 11.8k  (hidden comment: RC0603FR-0711K8L)
RES, 11.8 k, 1%, 0.1 W, 0603; Manufacturer: Yageo America; CompType: Resistor; Value: 11.8k; Res_ohm: 11800; Value_Code: 11k8; Tolerance_%: 1; Power_W: 0.1; Value2: 0.1W; VDC_V: 150; TempCo: 200 ppm/C; SizeArea_mm2: 1.28; SizeX_mm: 1.6; SizeY_mm: 0.8; EIA_Code: E96; U/M: EA; AEC Category: Q200; Green_Lifecycle: Active; Green_REACh: Passed
signal-integrity model Resistor
simulation model Resistor
footprint 0603
footprint 0603M
footprint 0603L
footprint 0603_HV
footprint 0603S
pins: 1, 2

## RC0603FR-0711KL
designator R?  ValueDisplayed: 11.0k  (hidden comment: RC0603FR-0711KL)
RES, 11.0 k, 1%, 0.1 W, 0603; Manufacturer: Yageo America; CompType: Resistor; Value: 11.0k; Res_ohm: 11000; Value_Code: 11k0; Tolerance_%: 1; Power_W: 0.1; Value2: 0.1W; VDC_V: 150; TempCo: 200 ppm/C; SizeArea_mm2: 1.28; SizeX_mm: 1.6; SizeY_mm: 0.8; EIA_Code: E96; U/M: EA; AEC Category: Q200; Green_Lifecycle: Active; Green_REACh: Passed
signal-integrity model Resistor
simulation model Resistor
footprint 0603
footprint 0603M
footprint 0603L
footprint 0603_HV
footprint 0603S
pins: 1, 2

## RC0603FR-0711R3L
designator R?  ValueDisplayed: 11.3  (hidden comment: RC0603FR-0711R3L)
RES, 11.3, 1%, 0.1 W, 0603; Manufacturer: Yageo America; CompType: Resistor; Value: 11.3; Value_Code: 11R3; Tolerance_%: 1; Power_W: 0.1; Value2: 0.1W; VDC_V: 150; TempCo: 200 ppm/C; SizeArea_mm2: 1.28; SizeX_mm: 1.6; SizeY_mm: 0.8; EIA_Code: E96; U/M: EA; AEC Category: Q200
signal-integrity model Resistor
simulation model Resistor
footprint 0603
footprint 0603M
footprint 0603L
footprint 0603_HV
footprint 0603S
pins: 1, 2

## RC0603FR-0711R5L
designator R?  ValueDisplayed: 11.5  (hidden comment: RC0603FR-0711R5L)
RES, 11.5, 1%, 0.1 W, 0603; Manufacturer: Yageo America; CompType: Resistor; Value: 11.5; Value_Code: 11R5; Tolerance_%: 1; Power_W: 0.1; Value2: 0.1W; VDC_V: 150; TempCo: 200 ppm/C; SizeArea_mm2: 1.28; SizeX_mm: 1.6; SizeY_mm: 0.8; EIA_Code: E96; U/M: EA; AEC Category: Q200
signal-integrity model Resistor
simulation model Resistor
footprint 0603
footprint 0603M
footprint 0603L
footprint 0603_HV
footprint 0603S
pins: 1, 2

## RC0603FR-0711R8L
designator R?  ValueDisplayed: 11.8  (hidden comment: RC0603FR-0711R8L)
RES, 11.8, 1%, 0.1 W, 0603; Manufacturer: Yageo America; CompType: Resistor; Value: 11.8; Value_Code: 11R8; Tolerance_%: 1; Power_W: 0.1; Value2: 0.1W; VDC_V: 150; TempCo: 200 ppm/C; SizeArea_mm2: 1.28; SizeX_mm: 1.6; SizeY_mm: 0.8; EIA_Code: E96; U/M: EA; AEC Category: Q200
signal-integrity model Resistor
simulation model Resistor
footprint 0603
footprint 0603M
footprint 0603L
footprint 0603_HV
footprint 0603S
pins: 1, 2

## RC0603FR-0711RL
designator R?  ValueDisplayed: 11.0  (hidden comment: RC0603FR-0711RL)
RES, 11.0, 1%, 0.1 W, 0603; Manufacturer: Yageo America; CompType: Resistor; Value: 11.0; Res_ohm: 11; Value_Code: 11R0; Tolerance_%: 1; Power_W: 0.1; Value2: 0.1W; VDC_V: 150; TempCo: 200 ppm/C; SizeArea_mm2: 1.28; SizeX_mm: 1.6; SizeY_mm: 0.8; EIA_Code: E96; U/M: EA; AEC Category: Q200
signal-integrity model Resistor
simulation model Resistor
footprint 0603
footprint 0603M
footprint 0603L
footprint 0603_HV
footprint 0603S
pins: 1, 2

## RC0603FR-0712K1L
designator R?  ValueDisplayed: 12.1k  (hidden comment: RC0603FR-0712K1L)
RES, 12.1 k, 1%, 0.1 W, 0603; Manufacturer: Yageo America; CompType: Resistor; Value: 12.1k; Res_ohm: 12100; Value_Code: 12k1; Tolerance_%: 1; Power_W: 0.1; Value2: 0.1W; VDC_V: 150; TempCo: 200 ppm/C; SizeArea_mm2: 1.28; SizeX_mm: 1.6; SizeY_mm: 0.8; EIA_Code: E96; U/M: EA; AEC Category: Q200; Green_Lifecycle: Active; Green_REACh: Passed
signal-integrity model Resistor
simulation model Resistor
footprint 0603
footprint 0603M
footprint 0603L
footprint 0603_HV
footprint 0603S
pins: 1, 2

## RC0603FR-0712K4L
designator R?  ValueDisplayed: 12.4k  (hidden comment: RC0603FR-0712K4L)
RES, 12.4 k, 1%, 0.1 W, 0603; Manufacturer: Yageo America; CompType: Resistor; Value: 12.4k; Res_ohm: 12400; Value_Code: 12k4; Tolerance_%: 1; Power_W: 0.1; Value2: 0.1W; VDC_V: 150; TempCo: 200 ppm/C; SizeArea_mm2: 1.28; SizeX_mm: 1.6; SizeY_mm: 0.8; EIA_Code: E96; U/M: EA; AEC Category: Q200
signal-integrity model Resistor
simulation model Resistor
footprint 0603
footprint 0603M
footprint 0603L
footprint 0603_HV
footprint 0603S
pins: 1, 2

## RC0603FR-0712K7L
designator R?  ValueDisplayed: 12.7k  (hidden comment: RC0603FR-0712K7L)
RES, 12.7 k, 1%, 0.1 W, 0603; Manufacturer: Yageo America; CompType: Resistor; Value: 12.7k; Res_ohm: 12700; Value_Code: 12k7; Tolerance_%: 1; Power_W: 0.1; Value2: 0.1W; VDC_V: 150; TempCo: 200 ppm/C; SizeArea_mm2: 1.28; SizeX_mm: 1.6; SizeY_mm: 0.8; EIA_Code: E96; U/M: EA; AEC Category: Q200; Green_Lifecycle: Active; Green_REACh: Passed
signal-integrity model Resistor
simulation model Resistor
footprint 0603
footprint 0603M
footprint 0603L
footprint 0603_HV
footprint 0603S
pins: 1, 2

## RC0603FR-0712KL
designator R?  ValueDisplayed: 12.0k  (hidden comment: RC0603FR-0712KL)
RES, 12.0 k, 1%, 0.1 W, 0603; Manufacturer: Yageo America; CompType: Resistor; Value: 12.0k; Res_ohm: 12000; Value_Code: 12k0; Tolerance_%: 1; Power_W: 0.1; Value2: 0.1W; VDC_V: 150; TempCo: 200 ppm/C; SizeArea_mm2: 1.28; SizeX_mm: 1.6; SizeY_mm: 0.8; U/M: EA; AEC Category: Q200; Green_Lifecycle: Active; Green_REACh: Passed
signal-integrity model Resistor
simulation model Resistor
footprint 0603
footprint 0603M
footprint 0603L
footprint 0603_HV
footprint 0603S
pins: 1, 2

## RC0603FR-0712R1L
designator R?  ValueDisplayed: 12.1  (hidden comment: RC0603FR-0712R1L)
RES, 12.1, 1%, 0.1 W, 0603; Manufacturer: Yageo America; CompType: Resistor; Value: 12.1; Value_Code: 12R1; Tolerance_%: 1; Power_W: 0.1; Value2: 0.1W; VDC_V: 150; TempCo: 200 ppm/C; SizeArea_mm2: 1.28; SizeX_mm: 1.6; SizeY_mm: 0.8; EIA_Code: E96; U/M: EA; AEC Category: Q200
signal-integrity model Resistor
simulation model Resistor
footprint 0603
footprint 0603M
footprint 0603L
footprint 0603_HV
footprint 0603S
pins: 1, 2

## RC0603FR-0712R4L
designator R?  ValueDisplayed: 12.4  (hidden comment: RC0603FR-0712R4L)
RES, 12.4, 1%, 0.1 W, 0603; Manufacturer: Yageo America; CompType: Resistor; Value: 12.4; Value_Code: 12R4; Tolerance_%: 1; Power_W: 0.1; Value2: 0.1W; VDC_V: 150; TempCo: 200 ppm/C; SizeArea_mm2: 1.28; SizeX_mm: 1.6; SizeY_mm: 0.8; EIA_Code: E96; U/M: EA; AEC Category: Q200
signal-integrity model Resistor
simulation model Resistor
footprint 0603
footprint 0603M
footprint 0603L
footprint 0603_HV
footprint 0603S
pins: 1, 2

## RC0603FR-0712R7L
designator R?  ValueDisplayed: 12.7  (hidden comment: RC0603FR-0712R7L)
RES, 12.7, 1%, 0.1 W, 0603; Manufacturer: Yageo America; CompType: Resistor; Value: 12.7; Value_Code: 12R7; Tolerance_%: 1; Power_W: 0.1; Value2: 0.1W; VDC_V: 150; TempCo: 200 ppm/C; SizeArea_mm2: 1.28; SizeX_mm: 1.6; SizeY_mm: 0.8; EIA_Code: E96; U/M: EA; AEC Category: Q200
signal-integrity model Resistor
simulation model Resistor
footprint 0603
footprint 0603M
footprint 0603L
footprint 0603_HV
footprint 0603S
pins: 1, 2

## RC0603FR-0712RL
designator R?  ValueDisplayed: 12.0  (hidden comment: RC0603FR-0712RL)
RES, 12.0, 1%, 0.1 W, 0603; Manufacturer: Yageo America; CompType: Resistor; Value: 12.0; Res_ohm: 12; Value_Code: 12R0; Tolerance_%: 1; Power_W: 0.1; Value2: 0.1W; VDC_V: 150; TempCo: 200 ppm/C; SizeArea_mm2: 1.28; SizeX_mm: 1.6; SizeY_mm: 0.8; U/M: EA; AEC Category: Q200; Green_Lifecycle: Active; Green_REACh: Passed
signal-integrity model Resistor
simulation model Resistor
footprint 0603
footprint 0603M
footprint 0603L
footprint 0603_HV
footprint 0603S
pins: 1, 2

## RC0603FR-0713K3L
designator R?  ValueDisplayed: 13.3k  (hidden comment: RC0603FR-0713K3L)
RES, 13.3 k, 1%, 0.1 W, 0603; Manufacturer: Yageo America; CompType: Resistor; Value: 13.3k; Res_ohm: 13300; Value_Code: 13k3; Tolerance_%: 1; Power_W: 0.1; Value2: 0.1W; VDC_V: 150; TempCo: 200 ppm/C; SizeArea_mm2: 1.28; SizeX_mm: 1.6; SizeY_mm: 0.8; EIA_Code: E96; U/M: EA; AEC Category: Q200
signal-integrity model Resistor
simulation model Resistor
footprint 0603
footprint 0603M
footprint 0603L
footprint 0603_HV
footprint 0603S
pins: 1, 2

## RC0603FR-0713K7L
designator R?  ValueDisplayed: 13.7k  (hidden comment: RC0603FR-0713K7L)
RES, 13.7 k, 1%, 0.1 W, 0603; Manufacturer: Yageo America; CompType: Resistor; Value: 13.7k; Res_ohm: 13700; Value_Code: 13k7; Tolerance_%: 1; Power_W: 0.1; Value2: 0.1W; VDC_V: 150; TempCo: 200 ppm/C; SizeArea_mm2: 1.28; SizeX_mm: 1.6; SizeY_mm: 0.8; EIA_Code: E96; U/M: EA; AEC Category: Q200; Green_Lifecycle: Active; Green_REACh: Passed
signal-integrity model Resistor
simulation model Resistor
footprint 0603
footprint 0603M
footprint 0603L
footprint 0603_HV
footprint 0603S
pins: 1, 2

## RC0603FR-0713KL
designator R?  ValueDisplayed: 13.0k  (hidden comment: RC0603FR-0713KL)
RES, 13.0 k, 1%, 0.1 W, 0603; Manufacturer: Yageo America; CompType: Resistor; Value: 13.0k; Res_ohm: 13000; Value_Code: 13k0; Tolerance_%: 1; Power_W: 0.1; Value2: 0.1W; VDC_V: 150; TempCo: 200 ppm/C; SizeArea_mm2: 1.28; SizeX_mm: 1.6; SizeY_mm: 0.8; EIA_Code: E96; U/M: EA; AEC Category: Q200; Green_Lifecycle: Active; Green_REACh: Passed
signal-integrity model Resistor
simulation model Resistor
footprint 0603
footprint 0603M
footprint 0603L
footprint 0603_HV
footprint 0603S
pins: 1, 2

## RC0603FR-0713R3L
designator R?  ValueDisplayed: 13.3  (hidden comment: RC0603FR-0713R3L)
RES, 13.3, 1%, 0.1 W, 0603; Manufacturer: Yageo America; CompType: Resistor; Value: 13.3; Value_Code: 13R3; Tolerance_%: 1; Power_W: 0.1; Value2: 0.1W; VDC_V: 150; TempCo: 200 ppm/C; SizeArea_mm2: 1.28; SizeX_mm: 1.6; SizeY_mm: 0.8; EIA_Code: E96; U/M: EA; AEC Category: Q200
signal-integrity model Resistor
simulation model Resistor
footprint 0603
footprint 0603M
footprint 0603L
footprint 0603_HV
footprint 0603S
pins: 1, 2

## RC0603FR-0713R7L
designator R?  ValueDisplayed: 13.7  (hidden comment: RC0603FR-0713R7L)
RES, 13.7, 1%, 0.1 W, 0603; Manufacturer: Yageo America; CompType: Resistor; Value: 13.7; Value_Code: 13R7; Tolerance_%: 1; Power_W: 0.1; Value2: 0.1W; VDC_V: 150; TempCo: 200 ppm/C; SizeArea_mm2: 1.28; SizeX_mm: 1.6; SizeY_mm: 0.8; EIA_Code: E96; U/M: EA; AEC Category: Q200
signal-integrity model Resistor
simulation model Resistor
footprint 0603
footprint 0603M
footprint 0603L
footprint 0603_HV
footprint 0603S
pins: 1, 2

## RC0603FR-0713RL
designator R?  ValueDisplayed: 13.0  (hidden comment: RC0603FR-0713RL)
RES, 13.0, 1%, 0.1 W, 0603; Manufacturer: Yageo America; CompType: Resistor; Value: 13.0; Res_ohm: 13; Value_Code: 13R0; Tolerance_%: 1; Power_W: 0.1; Value2: 0.1W; VDC_V: 150; TempCo: 200 ppm/C; SizeArea_mm2: 1.28; SizeX_mm: 1.6; SizeY_mm: 0.8; EIA_Code: E96; U/M: EA; AEC Category: Q200
signal-integrity model Resistor
simulation model Resistor
footprint 0603
footprint 0603M
footprint 0603L
footprint 0603_HV
footprint 0603S
pins: 1, 2

## RC0603FR-0714K3L
designator R?  ValueDisplayed: 14.3k  (hidden comment: RC0603FR-0714K3L)
RES, 14.3 k, 1%, 0.1 W, 0603; Manufacturer: Yageo America; CompType: Resistor; Value: 14.3k; Res_ohm: 14300; Value_Code: 14k3; Tolerance_%: 1; Power_W: 0.1; Value2: 0.1W; VDC_V: 150; TempCo: 200 ppm/C; SizeArea_mm2: 1.28; SizeX_mm: 1.6; SizeY_mm: 0.8; EIA_Code: E96; U/M: EA; AEC Category: Q200; Green_Lifecycle: Active; Green_REACh: Passed
signal-integrity model Resistor
simulation model Resistor
footprint 0603
footprint 0603M
footprint 0603L
footprint 0603_HV
footprint 0603S
pins: 1, 2

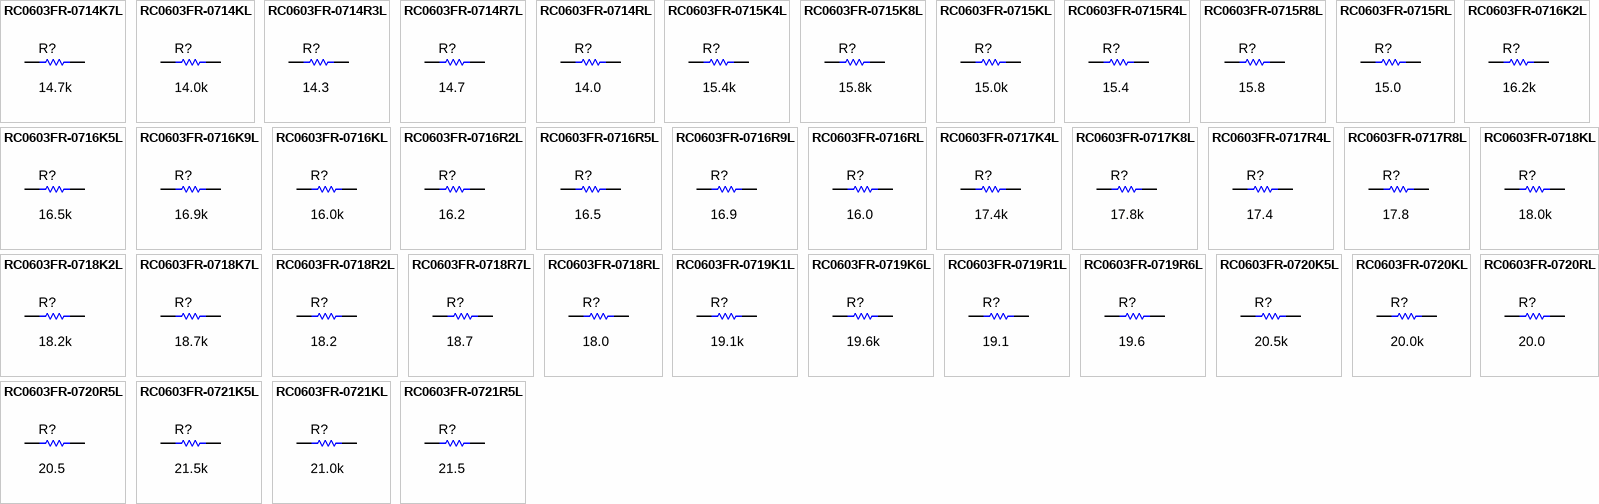
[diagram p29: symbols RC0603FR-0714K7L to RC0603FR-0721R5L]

## RC0603FR-0714K7L
designator R?  ValueDisplayed: 14.7k  (hidden comment: RC0603FR-0714K7L)
RES, 14.7 k, 1%, 0.1 W, 0603; Manufacturer: Yageo America; CompType: Resistor; Value: 14.7k; Res_ohm: 14700; Value_Code: 14k7; Tolerance_%: 1; Power_W: 0.1; Value2: 0.1W; VDC_V: 150; TempCo: 200 ppm/C; SizeArea_mm2: 1.28; SizeX_mm: 1.6; SizeY_mm: 0.8; EIA_Code: E96; U/M: EA; AEC Category: Q200; Green_Lifecycle: Active; Green_REACh: Passed
signal-integrity model Resistor
simulation model Resistor
footprint 0603
footprint 0603M
footprint 0603L
footprint 0603_HV
footprint 0603S
pins: 1, 2

## RC0603FR-0714KL
designator R?  ValueDisplayed: 14.0k  (hidden comment: RC0603FR-0714KL)
RES, 14.0 k, 1%, 0.1 W, 0603; Manufacturer: Yageo America; CompType: Resistor; Value: 14.0k; Res_ohm: 14000; Value_Code: 14k0; Tolerance_%: 1; Power_W: 0.1; Value2: 0.1W; VDC_V: 150; TempCo: 200 ppm/C; SizeArea_mm2: 1.28; SizeX_mm: 1.6; SizeY_mm: 0.8; EIA_Code: E96; U/M: EA; AEC Category: Q200
signal-integrity model Resistor
simulation model Resistor
footprint 0603
footprint 0603M
footprint 0603L
footprint 0603_HV
footprint 0603S
pins: 1, 2

## RC0603FR-0714R3L
designator R?  ValueDisplayed: 14.3  (hidden comment: RC0603FR-0714R3L)
RES, 14.3, 1%, 0.1 W, 0603; Manufacturer: Yageo America; CompType: Resistor; Value: 14.3; Value_Code: 14R3; Tolerance_%: 1; Power_W: 0.1; Value2: 0.1W; VDC_V: 150; TempCo: 200 ppm/C; SizeArea_mm2: 1.28; SizeX_mm: 1.6; SizeY_mm: 0.8; EIA_Code: E96; U/M: EA; AEC Category: Q200
signal-integrity model Resistor
simulation model Resistor
footprint 0603
footprint 0603M
footprint 0603L
footprint 0603_HV
footprint 0603S
pins: 1, 2

## RC0603FR-0714R7L
designator R?  ValueDisplayed: 14.7  (hidden comment: RC0603FR-0714R7L)
RES, 14.7, 1%, 0.1 W, 0603; Manufacturer: Yageo America; CompType: Resistor; Value: 14.7; Value_Code: 14R7; Tolerance_%: 1; Power_W: 0.1; Value2: 0.1W; VDC_V: 150; TempCo: 200 ppm/C; SizeArea_mm2: 1.28; SizeX_mm: 1.6; SizeY_mm: 0.8; EIA_Code: E96; U/M: EA; AEC Category: Q200
signal-integrity model Resistor
simulation model Resistor
footprint 0603
footprint 0603M
footprint 0603L
footprint 0603_HV
footprint 0603S
pins: 1, 2

## RC0603FR-0714RL
designator R?  ValueDisplayed: 14.0  (hidden comment: RC0603FR-0714RL)
RES, 14.0, 1%, 0.1 W, 0603; Manufacturer: Yageo America; CompType: Resistor; Value: 14.0; Res_ohm: 14; Value_Code: 14R0; Tolerance_%: 1; Power_W: 0.1; Value2: 0.1W; VDC_V: 150; TempCo: 200 ppm/C; SizeArea_mm2: 1.28; SizeX_mm: 1.6; SizeY_mm: 0.8; EIA_Code: E96; U/M: EA; AEC Category: Q200
signal-integrity model Resistor
simulation model Resistor
footprint 0603
footprint 0603M
footprint 0603L
footprint 0603_HV
footprint 0603S
pins: 1, 2

## RC0603FR-0715K4L
designator R?  ValueDisplayed: 15.4k  (hidden comment: RC0603FR-0715K4L)
RES, 15.4 k, 1%, 0.1 W, 0603; Manufacturer: Yageo America; CompType: Resistor; Value: 15.4k; Res_ohm: 15400; Value_Code: 15k4; Tolerance_%: 1; Power_W: 0.1; Value2: 0.1W; VDC_V: 150; TempCo: 200 ppm/C; SizeArea_mm2: 1.28; SizeX_mm: 1.6; SizeY_mm: 0.8; EIA_Code: E96; U/M: EA; AEC Category: Q200
signal-integrity model Resistor
simulation model Resistor
footprint 0603
footprint 0603M
footprint 0603L
footprint 0603_HV
footprint 0603S
pins: 1, 2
